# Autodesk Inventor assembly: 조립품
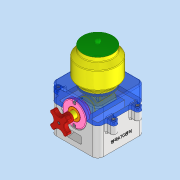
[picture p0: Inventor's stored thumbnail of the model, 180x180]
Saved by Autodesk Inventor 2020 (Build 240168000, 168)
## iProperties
Created: 2022-03
Part Number: 조립품
Document SubType Name: Assembly
Designer: Administrator
Author: Administrator
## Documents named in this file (11)
- C:\Users\Administrator\Desktop\720306V1012\조립품.iam
- C:\Users\Administrator\Desktop\720306V1012\베어링 부시.ipt
- C:\Users\Administrator\Desktop\720306V1012\본체.ipt
- C:\Users\Administrator\Desktop\720306V1012\본체커버.ipt
- C:\Users\Administrator\Desktop\720306V1012\볼트 M3x12.ipt
- C:\Users\Administrator\Desktop\720306V1012\볼트 M4x12.ipt
- C:\Users\Administrator\Desktop\720306V1012\앞커버.ipt
- C:\Users\Administrator\Desktop\720306V1012\용기.ipt
- C:\Users\Administrator\Desktop\720306V1012\용기캡.ipt
- C:\Users\Administrator\Desktop\720306V1012\핸들.ipt
- C:\Users\Administrator\Desktop\720306V1012\핸들축.ipt
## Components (2 placed, 2 different names)
1. 핸들:1
2. 핸들축:1
